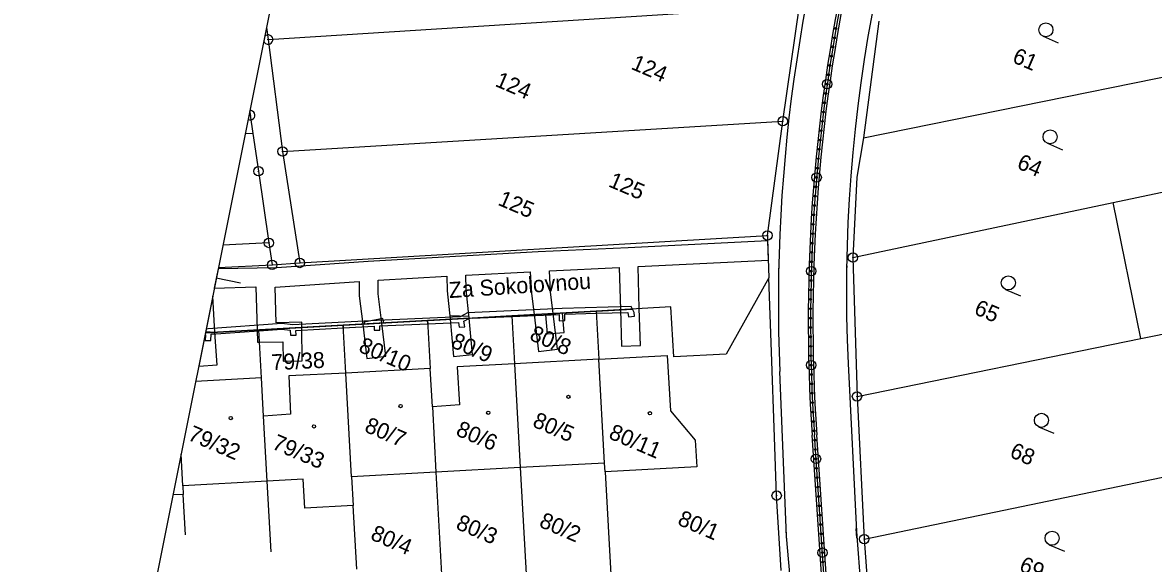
# Model space of a CAD drawing. Extents: x -548552 to -543113, y -1131925 to -1123599.
# Drawn here: x -548295.9 to -548175.4, y -1130809.3 to -1130751.8 of the extents above; entities that cross this region are included whole.
import ezdxf

# ---------------------------------------------------------------- set-up
doc = ezdxf.new("R2010")
doc.units = 0
for name, color, linetype in [('Hranice parcel', 7, 'Continuous'), ('Parcelní čísla', 7, 'Continuous'), ('Pop  PČ popisy', 7, 'Continuous'), ('Profile', 7, 'Continuous'), ('PROFILY NÁVRH', 7, 'Continuous'), ('Section', 7, 'Continuous'), ('STANIČENÍ', 7, 'Continuous'), ('Věcná břemena k části', 7, 'Continuous'), ('Značky bodu BP', 7, 'Continuous'), ('Značky budov', 7, 'Continuous'), ('Značky kultur', 7, 'Continuous')]:
    doc.layers.add(name, color=color, linetype=linetype)

msp = doc.modelspace()

# ---------------------------------------------------------------- linework, layer by layer
at = {"layer": 'Hranice parcel'}
for p, q in [((-548269.75, -1130753.57), (-548213.15, -1130750)), ((-548214.93, -1130762.27), (-548213.15, -1130750)), ((-548204.7, -1130751.62), (-548206.34, -1130764.02)), ((-548269.93, -1130752.3), (-548269.75, -1130753.57)), ((-548269.75, -1130753.57), (-548268.22, -1130765.48)), ((-548206.34, -1130764.02), (-548169.71, -1130756.61)), ((-548268.22, -1130765.48), (-548214.93, -1130762.27)), ((-548216.56, -1130774.42), (-548214.93, -1130762.27)), ((-548271.37, -1130763.56), (-548272.19, -1130763.6)), ((-548268.22, -1130765.48), (-548266.39, -1130777.36)), ((-548207.45, -1130776.79), (-548179.73, -1130770.93)), ((-548176.78, -1130785.4), (-548179.73, -1130770.93)), ((-548266.39, -1130777.36), (-548216.56, -1130774.42)), ((-548269.67, -1130775.23), (-548269.33, -1130777.57)), ((-548207.45, -1130776.79), (-548207.02, -1130791.57)), ((-548269.33, -1130777.57), (-548266.39, -1130777.36)), ((-548252.78, -1130783.48), (-548243.79, -1130782.98)), ((-548243.79, -1130782.98), (-548234.81, -1130782.48)), ((-548243.79, -1130782.98), (-548243.52, -1130788.1)), ((-548234.81, -1130782.48), (-548234.52, -1130787.6)), ((-548270.75, -1130784.49), (-548261.76, -1130783.99)), ((-548261.76, -1130783.99), (-548252.78, -1130783.48)), ((-548261.48, -1130789.08), (-548261.76, -1130783.99)), ((-548252.78, -1130783.48), (-548252.5, -1130788.59)), ((-548176.78, -1130785.4), (-548171.18, -1130784.26)), ((-548276.44, -1130784.8), (-548270.75, -1130784.49)), ((-548270.47, -1130789.58), (-548270.75, -1130784.49)), ((-548207.02, -1130791.57), (-548176.78, -1130785.4)), ((-548234.52, -1130787.6), (-548243.52, -1130788.1)), ((-548233.91, -1130798.68), (-548234.52, -1130787.6)), ((-548252.5, -1130788.59), (-548261.48, -1130789.08)), ((-548260.86, -1130800.12), (-548261.48, -1130789.08)), ((-548252.26, -1130792.67), (-548252.5, -1130788.59)), ((-548243.52, -1130788.1), (-548242.89, -1130799.13)), ((-548270.47, -1130789.58), (-548277.48, -1130789.96)), ((-548270.24, -1130793.67), (-548270.47, -1130789.58)), ((-548252.26, -1130792.67), (-548251.88, -1130799.62)), ((-548207.02, -1130791.57), (-548206.25, -1130806.76)), ((-548269.85, -1130800.6), (-548270.24, -1130793.67)), ((-548278.84, -1130801.07), (-548279.03, -1130797.71)), ((-548233.91, -1130798.68), (-548242.89, -1130799.13)), ((-548233.85, -1130799.61), (-548233.91, -1130798.68)), ((-548251.88, -1130799.62), (-548260.86, -1130800.12)), ((-548242.89, -1130799.13), (-548251.88, -1130799.62)), ((-548251.88, -1130799.62), (-548251.2, -1130811.77)), ((-548242.89, -1130799.13), (-548242.19, -1130811.72)), ((-548233.85, -1130799.61), (-548233.2, -1130811.18)), ((-548206.25, -1130806.76), (-548170.4, -1130799.32)), ((-548269.85, -1130800.6), (-548278.84, -1130801.07)), ((-548278.84, -1130801.07), (-548278.79, -1130802)), ((-548269.43, -1130808.12), (-548269.85, -1130800.6)), ((-548260.86, -1130800.12), (-548260.69, -1130803.17)), ((-548278.79, -1130802), (-548279.9, -1130802.06)), ((-548278.55, -1130806.29), (-548278.79, -1130802)), ((-548260.32, -1130809.94), (-548260.69, -1130803.17)), ((-548206.25, -1130806.76), (-548205.34, -1130818.85))]:
    msp.add_line(p, q, dxfattribs=at)
for points in [[(-548271.72, -1130761.23), (-548271.66, -1130761.63), (-548271.37, -1130763.56)], [(-548271.37, -1130763.56), (-548270.79, -1130767.6), (-548269.67, -1130775.23)], [(-548206.34, -1130764.02), (-548207.03, -1130768.22), (-548207.45, -1130776.79)], [(-548179.73, -1130770.93), (-548168.96, -1130768.66), (-548167.34, -1130768.3)], [(-548216.56, -1130774.42), (-548216.54, -1130774.81), (-548216.4, -1130778.95)], [(-548269.67, -1130775.23), (-548274.57, -1130775.48)], [(-548275.05, -1130777.85), (-548269.33, -1130777.57)], [(-548216.4, -1130778.95), (-548220.96, -1130787.05), (-548226.54, -1130787.36), (-548226.84, -1130782.03), (-548234.81, -1130782.48)], [(-548215.11, -1130810.11), (-548215.58, -1130802.13), (-548215.8, -1130795.92), (-548216.12, -1130786.81), (-548216.4, -1130778.95)], [(-548234.52, -1130787.6), (-548227.23, -1130787.21), (-548226.88, -1130793.09), (-548224.27, -1130796.24), (-548224.1, -1130799.07), (-548233.85, -1130799.61)], [(-548261.48, -1130789.08), (-548267.56, -1130789.38), (-548267.36, -1130793.44), (-548270.24, -1130793.67)], [(-548243.52, -1130788.1), (-548249.61, -1130788.43), (-548249.38, -1130792.47), (-548252.26, -1130792.67)], [(-548260.69, -1130803.17), (-548265.84, -1130803.45), (-548266.03, -1130800.39), (-548269.85, -1130800.6)]]:
    msp.add_lwpolyline(points, dxfattribs=at)
at = {"layer": 'Profile'}
for p, q in [((-548249.7, -1130651.36), (-548272.8, -1130766.65)), ((-548249.7, -1130651.36), (-548272.8, -1130766.65)), ((-548272.8, -1130766.65), (-548295.91, -1130881.93)), ((-548272.8, -1130766.65), (-548295.91, -1130881.93)), ((-548272.8, -1130766.65), (-548295.91, -1130881.93)), ((-548272.69, -1130779.5), (-548275.28, -1130778.98))]:
    msp.add_line(p, q, dxfattribs=at)
at = {"layer": 'PROFILY NÁVRH'}
for p, q in [((-548214.53, -1130806.44), (-548215.25, -1130788.91)), ((-548207.95, -1130788.06), (-548207.08, -1130805.94)), ((-548207.47, -1130859.94), (-548211.81, -1130795.68)), ((-548206.97, -1130859.91), (-548211.31, -1130795.65)), ((-548207.08, -1130805.94), (-548205.01, -1130833.74)), ((-548212.07, -1130834.22), (-548214.53, -1130806.44))]:
    msp.add_line(p, q, dxfattribs=at)
for centre, radius, start, end in [((-548048.23, -1130780.27), 159.92, 154.1881, 182.7922), ((-548041.26, -1130781.74), 174.14, 160.4533, 182.3604)]:
    msp.add_arc(centre, radius, start, end, dxfattribs=at)
for major_axis in [(-89.5, -156.46), (-89.26, -156.02)]:
    msp.add_ellipse((-548031.97, -1130783.52), major_axis=major_axis, ratio=0.999998, start_param=4.715662, end_param=5.299528, dxfattribs=at)
at = {"layer": 'STANIČENÍ'}
for p, q in [((-548207.22, -1130859.92), (-548211.56, -1130795.67)), ((-548214.5, -1130806.95), (-548214.57, -1130805.85)), ((-548207.04, -1130806.67), (-548207.11, -1130805.64))]:
    msp.add_line(p, q, dxfattribs=at)
for centre, radius in [((-548209.26, -1130752.39), 0.1), ((-548209.43, -1130753.38), 0.1), ((-548209.75, -1130755.35), 0.1), ((-548209.59, -1130754.36), 0.1), ((-548209.91, -1130756.34), 0.1), ((-548210.05, -1130757.33), 0.1), ((-548210.2, -1130758.32), 0.5), ((-548210.2, -1130758.32), 0.1), ((-548210.33, -1130759.31), 0.1), ((-548210.59, -1130761.29), 0.1), ((-548210.47, -1130760.3), 0.1), ((-548210.71, -1130762.28), 0.1), ((-548210.83, -1130763.28), 0.1), ((-548210.94, -1130764.27), 0.1), ((-548211.14, -1130766.26), 0.1), ((-548211.04, -1130765.26), 0.1), ((-548211.23, -1130767.26), 0.1), ((-548211.32, -1130768.25), 0.5), ((-548211.32, -1130768.25), 0.1), ((-548211.4, -1130769.25), 0.1), ((-548211.48, -1130770.25), 0.1), ((-548211.62, -1130772.24), 0.1), ((-548211.55, -1130771.24), 0.1), ((-548211.68, -1130773.24), 0.1), ((-548211.73, -1130774.24), 0.1), ((-548211.78, -1130775.24), 0.1), ((-548211.82, -1130776.23), 0.1), ((-548211.89, -1130778.23), 0.5), ((-548211.89, -1130778.23), 0.1), ((-548211.86, -1130777.23), 0.1), ((-548211.92, -1130779.23), 0.1), ((-548211.94, -1130780.23), 0.1), ((-548211.96, -1130781.23), 0.1), ((-548211.97, -1130782.23), 0.1), ((-548211.97, -1130783.23), 0.1), ((-548211.97, -1130784.23), 0.1), ((-548211.96, -1130785.23), 0.1), ((-548211.95, -1130786.23), 0.1), ((-548211.91, -1130788.23), 0.5), ((-548211.93, -1130787.23), 0.1), ((-548211.91, -1130788.23), 0.1), ((-548211.88, -1130789.23), 0.1), ((-548211.85, -1130790.23), 0.1), ((-548211.81, -1130791.23), 0.1), ((-548211.76, -1130792.23), 0.1), ((-548211.71, -1130793.23), 0.1), ((-548211.65, -1130794.23), 0.1), ((-548211.59, -1130795.22), 0.1), ((-548211.52, -1130796.22), 0.1), ((-548211.46, -1130797.22), 0.1), ((-548211.39, -1130798.22), 0.5), ((-548211.39, -1130798.22), 0.1), ((-548211.32, -1130799.22), 0.1), ((-548211.25, -1130800.21), 0.1), ((-548211.19, -1130801.21), 0.1), ((-548211.12, -1130802.21), 0.1), ((-548211.05, -1130803.21), 0.1), ((-548210.98, -1130804.2), 0.1), ((-548210.92, -1130805.2), 0.1), ((-548210.85, -1130806.2), 0.1), ((-548210.78, -1130807.2), 0.1), ((-548210.71, -1130808.2), 0.5), ((-548210.71, -1130808.2), 0.1), ((-548210.65, -1130809.19), 0.1)]:
    msp.add_circle(centre, radius, dxfattribs=at)
for major_axis, start_param, end_param in [((-89.38, -156.24), 4.715662, 5.299528), ((-91.11, -159.26), 5.199331, 5.201923), ((-87.51, -152.98), 5.198676, 5.202089)]:
    msp.add_ellipse((-548031.97, -1130783.52), major_axis=major_axis, ratio=0.999998, start_param=start_param, end_param=end_param, dxfattribs=at)
at = {"layer": 'Věcná břemena k části'}
for p, q in [((-548275.08, -1130777.99), (-548275.49, -1130780.03)), ((-548275.66, -1130780.89), (-548277.15, -1130788.33)), ((-548276.44, -1130784.81), (-548276.48, -1130785.01)), ((-548276.36, -1130784.39), (-548276.44, -1130784.8)), ((-548276.42, -1130784.68), (-548276.44, -1130784.81))]:
    msp.add_line(p, q, dxfattribs=at)
for points in [[(-548216.46, -1130777.06), (-548216.53, -1130774.99), (-548231.41, -1130775.73), (-548240.99, -1130776.19), (-548249.8, -1130776.66), (-548259.11, -1130777.2), (-548268.82, -1130777.86), (-548275.08, -1130777.99)], [(-548275.49, -1130780.03), (-548271.06, -1130779.91), (-548270.92, -1130784.49), (-548270.88, -1130785.78), (-548270.69, -1130785.78), (-548268.18, -1130785.74), (-548268.14, -1130787.81), (-548266.12, -1130787.78), (-548266.17, -1130784.23), (-548266.18, -1130783.67), (-548268.91, -1130783.72), (-548269.02, -1130779.94), (-548260.05, -1130779.33), (-548260.05, -1130780.87), (-548259.68, -1130783.87), (-548259.23, -1130787.52), (-548257.21, -1130787.28), (-548257.64, -1130783.76), (-548258.03, -1130780.63), (-548258.03, -1130779.2), (-548250.73, -1130778.77), (-548250.68, -1130780.31), (-548250.38, -1130783.35), (-548250, -1130787.3), (-548247.97, -1130787.1), (-548248.35, -1130783.24), (-548248.65, -1130780.2), (-548248.7, -1130778.66), (-548241.83, -1130778.3), (-548241.7, -1130780.61), (-548241.43, -1130782.85), (-548240.95, -1130786.77), (-548238.94, -1130786.52), (-548239.4, -1130782.73), (-548239.68, -1130780.44), (-548239.79, -1130778.19), (-548232.35, -1130777.84), (-548232.23, -1130782.33), (-548232.12, -1130786.21), (-548230.1, -1130786.15), (-548230.21, -1130782.22), (-548230.33, -1130777.74), (-548216.46, -1130777.06)], [(-548277.15, -1130788.33), (-548275.2, -1130788.21), (-548275.42, -1130784.75), (-548275.66, -1130780.89)], [(-548276.44, -1130784.8), (-548230.94, -1130782.27), (-548231.07, -1130782.01), (-548238.44, -1130782.22), (-548248.5, -1130782.66), (-548249.3, -1130783.09), (-548258.15, -1130783.47), (-548267.11, -1130783.96), (-548268.28, -1130783.79), (-548276.14, -1130784.38), (-548276.36, -1130784.39)], [(-548276.48, -1130785.01), (-548276.43, -1130785), (-548276.46, -1130785.62), (-548275.85, -1130785.6), (-548275.83, -1130784.95), (-548270.75, -1130784.57), (-548268.3, -1130784.39), (-548267.41, -1130784.52), (-548267.38, -1130785.06), (-548266.78, -1130785.06), (-548266.81, -1130784.54), (-548261.75, -1130784.26), (-548261.76, -1130783.99), (-548276.44, -1130784.81)], [(-548276.44, -1130784.81), (-548275.42, -1130784.75), (-548276.42, -1130784.68)]]:
    msp.add_lwpolyline(points, dxfattribs=at)
for points in [[(-548248.35, -1130783.24), (-548248.35, -1130783.06), (-548250.39, -1130782.99), (-548250.38, -1130783.35)], [(-548243.79, -1130783.05), (-548243.79, -1130782.98), (-548248.01, -1130783.22)], [(-548234.79, -1130782.72), (-548234.81, -1130782.48), (-548243.79, -1130782.98), (-548243.79, -1130783.05), (-548238.74, -1130782.83), (-548238.74, -1130783.53), (-548238.14, -1130783.48), (-548238.13, -1130782.81)], [(-548238.23, -1130784.75), (-548238.4, -1130782.71), (-548240.21, -1130782.87), (-548240.03, -1130784.9)], [(-548230.71, -1130783.03), (-548230.75, -1130782.62), (-548230.94, -1130782.27), (-548234.81, -1130782.48), (-548234.79, -1130782.72), (-548231.42, -1130782.63), (-548231.37, -1130783.09)], [(-548252.75, -1130783.83), (-548252.78, -1130783.48), (-548261.76, -1130783.99), (-548261.75, -1130784.26), (-548258.47, -1130784.08), (-548258.46, -1130784.52), (-548257.86, -1130784.51), (-548257.87, -1130784.05)], [(-548257.53, -1130783.27), (-548259.54, -1130783.65), (-548259.49, -1130783.86), (-548257.44, -1130783.74)], [(-548248.89, -1130783.55), (-548248.3, -1130783.23), (-548252.78, -1130783.48), (-548252.75, -1130783.83), (-548249.47, -1130783.69), (-548249.39, -1130784.19), (-548248.79, -1130784.17)]]:
    msp.add_lwpolyline(points, close=True, dxfattribs=at)
at = {"layer": 'Značky bodu BP'}
for p, q in [((-548270.11, -1130753.23), (-548270.22, -1130753.75)), ((-548271.7, -1130761.13), (-548271.89, -1130762.08))]:
    msp.add_line(p, q, dxfattribs=at)
for centre, radius in [((-548269.75, -1130753.57), 0.0303), ((-548271.66, -1130761.63), 0.0303), ((-548214.93, -1130762.27), 0.5), ((-548214.93, -1130762.27), 0.0303), ((-548268.22, -1130765.48), 0.5), ((-548268.22, -1130765.48), 0.0303), ((-548270.79, -1130767.6), 0.5), ((-548270.79, -1130767.6), 0.0303), ((-548216.56, -1130774.42), 0.5), ((-548216.56, -1130774.42), 0.0303), ((-548269.67, -1130775.23), 0.5), ((-548269.67, -1130775.23), 0.0303), ((-548266.39, -1130777.36), 0.5), ((-548207.45, -1130776.79), 0.5), ((-548207.45, -1130776.79), 0.0303), ((-548269.33, -1130777.57), 0.5), ((-548269.33, -1130777.57), 0.0303), ((-548266.39, -1130777.36), 0.0303), ((-548207.02, -1130791.57), 0.5), ((-548207.02, -1130791.57), 0.0303), ((-548215.58, -1130802.13), 0.5), ((-548215.58, -1130802.13), 0.0303), ((-548206.25, -1130806.76), 0.5), ((-548206.25, -1130806.76), 0.0303)]:
    msp.add_circle(centre, radius, dxfattribs=at)
for centre, start, end in [((-548269.75, -1130753.57), 200.3159, 137.0149), ((-548271.66, -1130761.63), 242.6038, 94.7269)]:
    msp.add_arc(centre, 0.5, start, end, dxfattribs=at)
at = {"layer": 'Značky budov'}
for centre in [(-548237.76, -1130791.61), (-548255.65, -1130792.6), (-548273.73, -1130793.88), (-548246.31, -1130793.3), (-548229.09, -1130793.36), (-548264.87, -1130794.76)]:
    msp.add_circle(centre, 0.175, dxfattribs=at)
at = {"layer": 'Značky kultur'}
for p, q in [((-548187.19, -1130753.23), (-548185.59, -1130753.92)), ((-548186.74, -1130764.62), (-548185.13, -1130765.31)), ((-548191.2, -1130780.17), (-548189.59, -1130780.86)), ((-548187.67, -1130794.8), (-548186.06, -1130795.49)), ((-548186.54, -1130807.35), (-548184.93, -1130808.04))]:
    msp.add_line(p, q, dxfattribs=at)
for centre in [(-548186.9, -1130752.54), (-548186.45, -1130763.93), (-548190.9, -1130779.48), (-548187.37, -1130794.11), (-548186.24, -1130806.66)]:
    msp.add_circle(centre, 0.75, dxfattribs=at)

# ---------------------------------------------------------------- texts
at = {"layer": 'Parcelní čísla'}
for s, rotation, p in [('124', 336.8058, (-548231.19, -1130756.67)), ('61', 336.8058, (-548190.58, -1130755.95)), ('124', 336.8058, (-548245.68, -1130758.49)), ('64', 336.8058, (-548190.09, -1130767.24)), ('125', 336.8058, (-548233.6, -1130769.18)), ('125', 336.8058, (-548245.38, -1130771.14)), ('65', 336.8058, (-548194.66, -1130782.75)), ('80/8', 336.8058, (-548242.01, -1130785.5)), ('80/10', 336.8058, (-548260.22, -1130786.76)), ('80/9', 336.8058, (-548250.39, -1130786.28)), ('79/38', 2.8058, (-548269.37, -1130788.79)), ('80/7', 336.8058, (-548259.6, -1130795.27)), ('80/5', 336.8058, (-548241.69, -1130794.73)), ('79/32', 336.8058, (-548278.42, -1130796.15)), ('80/6', 336.8058, (-548249.86, -1130795.66)), ('80/11', 336.8058, (-548233.58, -1130795.99)), ('79/33', 336.8058, (-548269.45, -1130797.09)), ('68', 336.8058, (-548190.86, -1130797.97)), ('80/3', 336.8058, (-548249.86, -1130805.62)), ('80/2', 336.8058, (-548240.99, -1130805.4)), ('80/1', 336.8058, (-548226.24, -1130805.18)), ('80/4', 336.8058, (-548258.96, -1130806.75)), ('69', 336.8058, (-548189.85, -1130810.09))]:
    msp.add_text(s, height=1.7, rotation=rotation, dxfattribs=at).set_placement(p)
at = {"layer": 'Pop  PČ popisy'}
msp.add_text('Za Sokolovnou', height=1.7, rotation=3.8058, dxfattribs=at).set_placement((-548250.45, -1130781.1))
at = {"layer": 'Section'}
msp.add_text('-', height=5.999999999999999e-12, rotation=29.9359, dxfattribs=at).set_placement((-548207.93, -1130797.19))

doc.saveas('drawing.dxf')
